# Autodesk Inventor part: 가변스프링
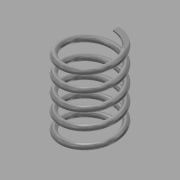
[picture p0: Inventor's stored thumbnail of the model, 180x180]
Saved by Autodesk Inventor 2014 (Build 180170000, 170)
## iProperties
Created: 2018-12
Part Number: 가변스프링
Material: Stainless Steel
Document SubType Name: Modeling
Designer: kh
Density: 8.08 g/cm^3
Appearance: Semi-Polished
Mass: 7.07161 g
Surface Area: 17.7587 cm^2
Volume: 0.875199 cm^3
Author: kh
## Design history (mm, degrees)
sketch "Sketch1"
  geometry: L1 (0, 0)-(9, 0); L2 (9, 0)-(9, 28.5); L3 (9, 28.5)-(0, 28.5); L4 (0, 28.5)-(0, 0); C1 r 1 at (9, 0)
  constraints: 8 end point, 2 parallel, 1 centre point, 1 coincident, 1 horizontal, 1 perpendicular
  dimensions: "d0" = 28.5 distance of L2.end L1.end (derived); "d1" = 18 diameter of L2 L4; "d2" = 2 diameter of C1
coil "Coil1" sketch "Sketch1" pitch "d3" = 10; turns "d5" = 5; dims "d4" = 28.5 (= d0), "d6" = 0, angle "d7" = 90 deg, angle "d8" = 90 deg, "d9" = 0, "d10" = 0
split "Split1"
workplane "Work Plane1"
split "Split2"
body "Solid1"
other parameters: "d11" = 28.5 (= d0)
